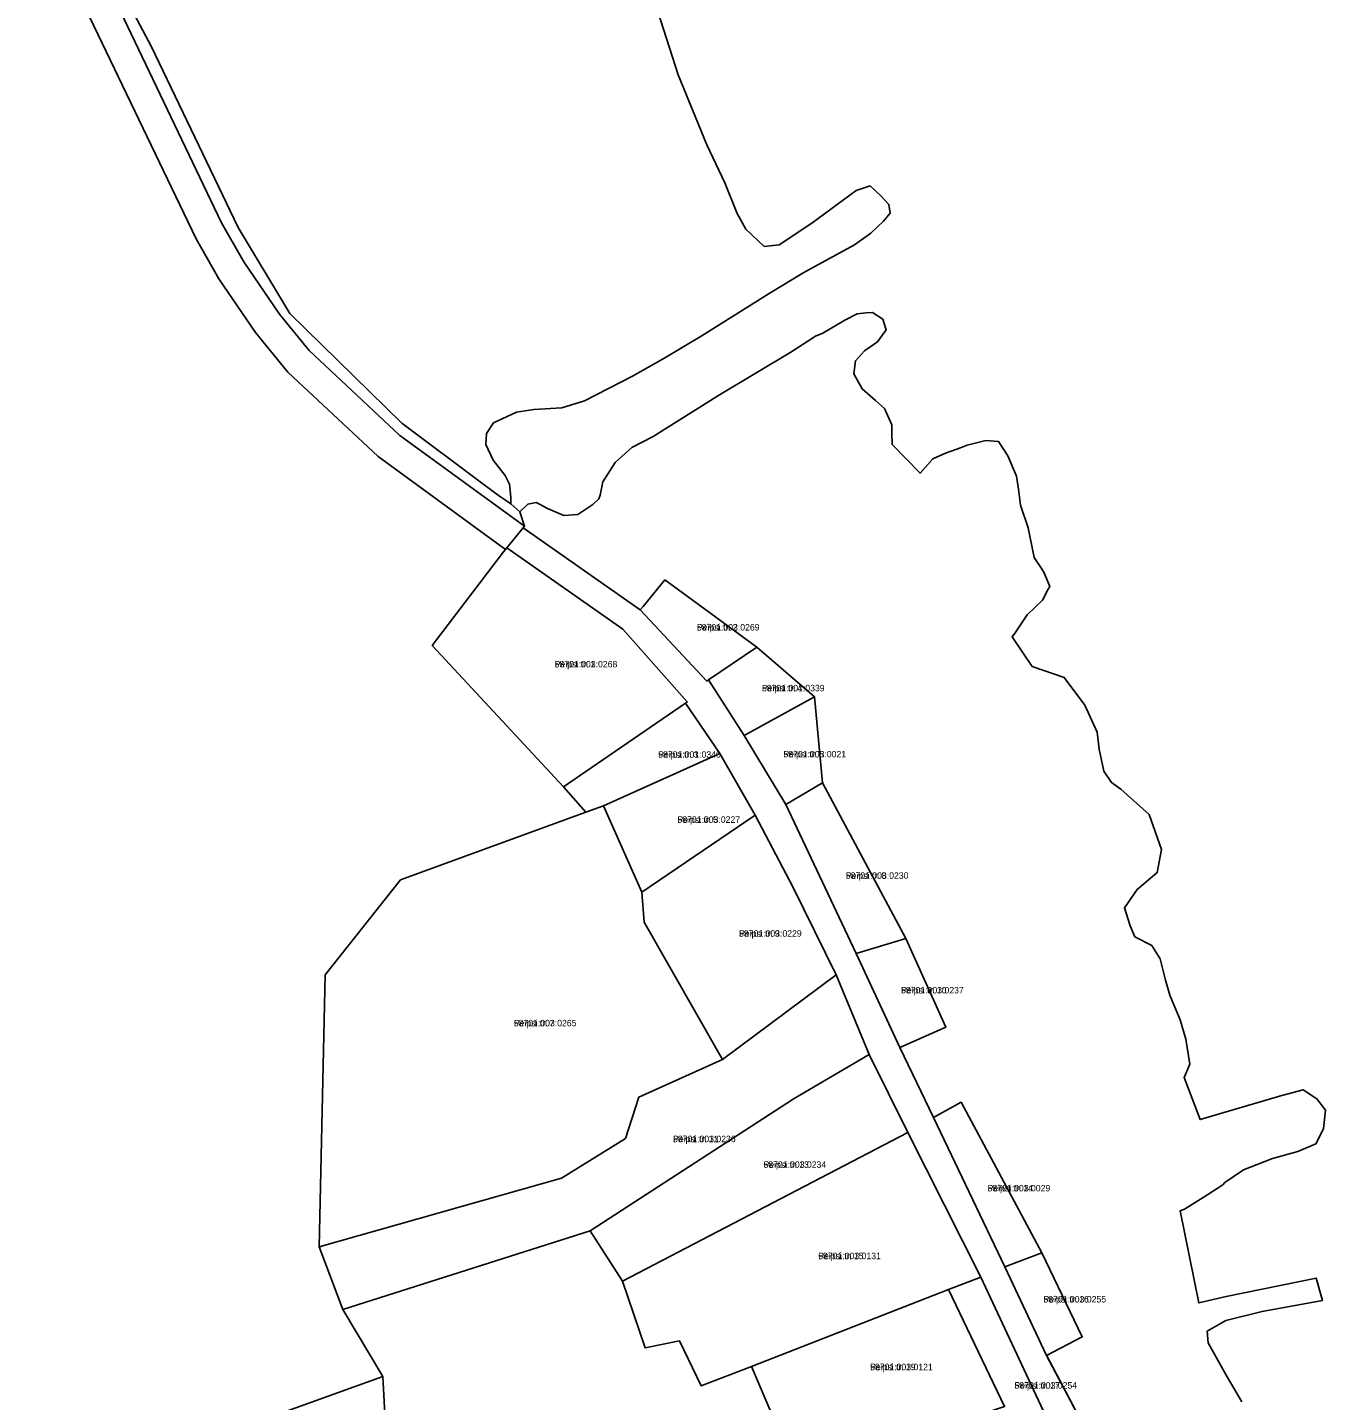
# Model space of a CAD drawing. Extents: x 663371 to 690098, y 6476568 to 6518353.
# Drawn here: x 687904.6 to 688205.1, y 6492520.5 to 6492838.4 of the extents above; entities that cross this region are included whole.
import ezdxf

# ---------------------------------------------------------------- set-up
doc = ezdxf.new("R2010")
doc.units = 0
for name, color, linetype in [('L_AADRESS', 7, 'Continuous'), ('PIIR', 7, 'Continuous'), ('TUNNUS', 7, 'Continuous')]:
    doc.layers.add(name, color=color, linetype=linetype)

msp = doc.modelspace()

# ---------------------------------------------------------------- linework, layer by layer
at = {"layer": 'PIIR'}
for points in [[(688049.77, 6492844.51), (688055.27, 6492827.42), (688061.86, 6492811.22), (688066.08, 6492802.43), (688068.94, 6492795.35), (688070.92, 6492791.66), (688075.15, 6492787.68), (688078.65, 6492788.09), (688086.21, 6492793.05), (688096.49, 6492800.61), (688099.67, 6492801.7), (688102.29, 6492799.35), (688104.01, 6492797.37), (688104.31, 6492795.41), (688102.77, 6492793.53), (688099.83, 6492790.75), (688096.07, 6492788.09), (688084.37, 6492781.68), (688076.35, 6492776.77), (688060.61, 6492766.88), (688051.8, 6492761.65), (688044.71, 6492757.64), (688033.59, 6492751.95), (688028.32, 6492750.34), (688021.86, 6492749.9), (688017.82, 6492749.35), (688012.52, 6492746.84), (688010.84, 6492744.37), (688010.74, 6492741.81), (688012.38, 6492738.22), (688015.2, 6492734.69), (688016.23, 6492732.65), (688016.48, 6492729.65), (688016.47, 6492728.13), (688015.77, 6492728.61), (688013.9, 6492729.9), (688010.04, 6492732.74), (687991.27, 6492746.81), (687965.32, 6492772.19), (687953.37, 6492792.06), (687933.3, 6492833.94), (687919.52, 6492859.99)], [(687919.52, 6492859.99), (687933.3, 6492833.94), (687953.37, 6492792.06), (687965.32, 6492772.19), (687991.27, 6492746.81), (688010.04, 6492732.74), (688013.9, 6492729.9), (688015.77, 6492728.61), (688016.47, 6492728.13), (688018.58, 6492726.23), (688019.67, 6492722.92), (687990.82, 6492743.9), (687969.78, 6492763.62), (687962.96, 6492772), (687954.7, 6492784.09), (687949.55, 6492793.19), (687925.27, 6492843.86)], [(687925.27, 6492843.86), (687949.55, 6492793.19), (687954.7, 6492784.09), (687962.96, 6492772), (687969.78, 6492763.62), (687990.82, 6492743.9), (688019.67, 6492722.92), (688019.36, 6492722.55), (688015.56, 6492717.9), (688015.25, 6492717.52), (687985.77, 6492739.07), (687964.9, 6492758.61), (687957.42, 6492767.74), (687948.89, 6492780.18), (687943.62, 6492789.47), (687919.02, 6492840.71)], [(687919.02, 6492840.71), (687943.62, 6492789.47), (687948.89, 6492780.18), (687957.42, 6492767.74), (687964.9, 6492758.61), (687985.77, 6492739.07), (688015.25, 6492717.52), (688014.84, 6492716.95), (687998.32, 6492695.33), (688028.7, 6492662.54), (688033.9, 6492656.68), (687990.98, 6492641.02), (687973.52, 6492619.07), (687972.11, 6492556.04), (687977.61, 6492541.58), (687986.85, 6492526.07), (687952.4, 6492513.63), (687860.02, 6492508.91)], [(688152.43, 6492508.44), (688140.62, 6492530.8), (688140.56, 6492530.91), (688148.8, 6492535.2), (688139.46, 6492554.68), (688120.75, 6492589.54), (688114.34, 6492586.01), (688106.61, 6492602.21), (688117.25, 6492606.93), (688107.96, 6492627.46), (688088.69, 6492663.47), (688086.82, 6492683.37), (688073.5, 6492694.93), (688052.19, 6492710.48), (688047.13, 6492704.29), (688046.49, 6492703.52), (688019.36, 6492722.55), (688019.67, 6492722.92), (688018.58, 6492726.23), (688020.46, 6492728.05), (688022.36, 6492728.38), (688023.15, 6492727.98), (688025.03, 6492727.04), (688028.76, 6492725.36), (688032, 6492725.63), (688035.52, 6492727.97), (688036.9, 6492729.22), (688037.19, 6492730.09), (688037.83, 6492733.17), (688040.63, 6492737.63), (688044.5, 6492741.11), (688049.47, 6492743.68), (688064.82, 6492753.35), (688081.32, 6492763.19), (688087.02, 6492766.91), (688088.78, 6492767.63), (688093.82, 6492770.64), (688096.67, 6492772.12), (688098.77, 6492772.3), (688100.25, 6492772.42), (688102.61, 6492770.84), (688103.25, 6492768.88), (688103.42, 6492768.36), (688101.37, 6492765.61), (688098.39, 6492763.53), (688096.29, 6492761.21), (688095.92, 6492758.16), (688097.82, 6492754.75), (688100.95, 6492752.03), (688103.01, 6492750.18), (688104.71, 6492746.35), (688104.75, 6492744.49), (688104.81, 6492741.85), (688111.25, 6492735.19), (688114.2, 6492738.5), (688117.18, 6492739.79), (688120.62, 6492741.03), (688122.14, 6492741.65), (688126.47, 6492742.72), (688129.45, 6492742.52), (688131.61, 6492739.17), (688133.61, 6492734.5), (688134.05, 6492731.49), (688134.48, 6492727.82), (688136.25, 6492722.57), (688137.67, 6492715.64), (688139.07, 6492713.55), (688139.94, 6492712.27), (688141.27, 6492708.97), (688140.95, 6492708.37), (688139.61, 6492705.76), (688136.09, 6492702.37), (688133.15, 6492697.97), (688132.58, 6492697.27), (688137.24, 6492690.46), (688144.65, 6492687.89), (688149.41, 6492681.45), (688152.3, 6492675.2), (688152.69, 6492671.32), (688153.8, 6492666.19), (688155.57, 6492663.57), (688157.72, 6492662.06), (688164.32, 6492656.15), (688167.19, 6492648.08), (688166.19, 6492642.71), (688161.5, 6492638.82), (688158.56, 6492634.52), (688159.94, 6492630.38), (688161, 6492627.84), (688164.89, 6492625.81), (688166.86, 6492622.75), (688168.09, 6492617.83), (688169.1, 6492614.31), (688169.88, 6492612.44), (688171.46, 6492608.64), (688172.77, 6492604.11), (688173.69, 6492598.38), (688172.4, 6492595.29), (688176.11, 6492585.54), (688195.01, 6492591.06), (688199.96, 6492592.42), (688203.11, 6492590.35), (688205.14, 6492587.74), (688204.7, 6492583.36), (688202.9, 6492579.92), (688198.76, 6492578.17), (688192.85, 6492576.52), (688186.14, 6492573.91), (688181.79, 6492570.97), (688181.35, 6492570.42), (688176.77, 6492567.48), (688172.51, 6492564.78), (688171.5, 6492564.42), (688175.82, 6492543.08), (688182.14, 6492544.52), (688202.96, 6492548.82), (688204.4, 6492543.61), (688190.49, 6492541.08), (688182.02, 6492539.01), (688177.77, 6492536.56), (688177.96, 6492533.83), (688180.94, 6492528.44), (688182.16, 6492526.32), (688183.13, 6492524.64), (688185.79, 6492520.2)], [(688139.77, 6492518.16), (688125.34, 6492549.07), (688108.45, 6492582.56), (688099.48, 6492600.59), (688091.87, 6492619.01), (688081.89, 6492639.28), (688073.08, 6492656.01), (688064.88, 6492670.29), (688056.94, 6492681.93), (688057.35, 6492682.21), (688042.45, 6492699.07), (688015.56, 6492717.9), (688019.36, 6492722.55), (688046.49, 6492703.52), (688061.87, 6492687.04), (688062.29, 6492687.32), (688070.57, 6492674.43), (688080.18, 6492658.44), (688096.49, 6492624.01), (688106.61, 6492602.21), (688114.34, 6492586.01), (688130.87, 6492551.39), (688140.56, 6492530.91), (688152.43, 6492508.44)]]:
    msp.add_lwpolyline(points, dxfattribs=at)
for points in [[(688056.94, 6492681.93), (688028.7, 6492662.54), (687998.32, 6492695.33), (688014.84, 6492716.95), (688015.25, 6492717.52), (688015.56, 6492717.9), (688042.45, 6492699.07), (688057.35, 6492682.21)], [(688047.13, 6492704.29), (688052.19, 6492710.48), (688073.5, 6492694.93), (688062.29, 6492687.32), (688061.87, 6492687.04), (688046.49, 6492703.52)], [(688062.29, 6492687.32), (688073.5, 6492694.93), (688086.82, 6492683.37), (688070.57, 6492674.43)], [(688028.7, 6492662.54), (688056.94, 6492681.93), (688064.88, 6492670.29), (688037.98, 6492658.17), (688033.9, 6492656.68)], [(688080.18, 6492658.44), (688070.57, 6492674.43), (688086.82, 6492683.37), (688088.69, 6492663.47)], [(688037.98, 6492658.17), (688064.88, 6492670.29), (688073.08, 6492656.01), (688046.83, 6492638.17)], [(688107.96, 6492627.46), (688096.49, 6492624.01), (688080.18, 6492658.44), (688088.69, 6492663.47)], [(688046.83, 6492638.17), (688047.38, 6492631.25), (688065.54, 6492599.41), (688046.12, 6492590.68), (688043.06, 6492581.18), (688028.21, 6492571.98), (687972.11, 6492556.04), (687973.52, 6492619.07), (687990.98, 6492641.02), (688033.9, 6492656.68), (688037.98, 6492658.17)], [(688046.83, 6492638.17), (688073.08, 6492656.01), (688081.89, 6492639.28), (688091.87, 6492619.01), (688065.54, 6492599.41), (688047.38, 6492631.25)], [(688117.25, 6492606.93), (688106.61, 6492602.21), (688096.49, 6492624.01), (688107.96, 6492627.46)], [(688065.54, 6492599.41), (688091.87, 6492619.01), (688099.48, 6492600.59), (688082.08, 6492590.41), (688034.88, 6492559.77), (687977.61, 6492541.58), (687972.11, 6492556.04), (688028.21, 6492571.98), (688043.06, 6492581.18), (688046.12, 6492590.68)], [(688082.08, 6492590.41), (688099.48, 6492600.59), (688108.45, 6492582.56), (688042.34, 6492548.11), (688034.88, 6492559.77)], [(688130.87, 6492551.39), (688114.34, 6492586.01), (688120.75, 6492589.54), (688139.46, 6492554.68)], [(688047.6, 6492532.68), (688042.34, 6492548.11), (688108.45, 6492582.56), (688125.34, 6492549.07), (688117.88, 6492546.17), (688072.21, 6492528.37), (688060.58, 6492523.84), (688055.58, 6492534.27)], [(687977.61, 6492541.58), (688034.88, 6492559.77), (688042.34, 6492548.11), (688047.6, 6492532.68), (688055.58, 6492534.27), (688060.58, 6492523.84), (688072.21, 6492528.37), (688080.45, 6492509), (688100.45, 6492508.81), (688091.5, 6492505.79), (688095.7, 6492497.39), (688072.78, 6492489.02), (688042.26, 6492489.34), (688040.92, 6492445.66), (688012.56, 6492458.29), (688017.36, 6492489.98), (688011.42, 6492506.84), (687987.57, 6492513.01), (687986.85, 6492526.07)], [(688140.56, 6492530.91), (688130.87, 6492551.39), (688139.46, 6492554.68), (688148.8, 6492535.2)], [(688139.77, 6492518.16), (688095.7, 6492497.39), (688091.5, 6492505.79), (688100.45, 6492508.81), (688130.83, 6492519.07), (688117.88, 6492546.17), (688125.34, 6492549.07)], [(688130.83, 6492519.07), (688100.45, 6492508.81), (688080.45, 6492509), (688072.21, 6492528.37), (688117.88, 6492546.17)], [(687955.96, 6492496.94), (687952.4, 6492513.63), (687986.85, 6492526.07), (687987.57, 6492513.01), (687988.32, 6492463.54), (687960.12, 6492464.96), (687956.75, 6492465.23), (687951.2, 6492466.48)]]:
    msp.add_lwpolyline(points, close=True, dxfattribs=at)

# ---------------------------------------------------------------- texts
at = {"layer": 'L_AADRESS'}
for s, p in [('Peipsi tn 2', (688059.59, 6492698.76)), ('Peipsi tn 1', (688026.66, 6492690.22)), ('Peipsi tn 4', (688074.65, 6492684.68)), ('Peipsi tn 3', (688050.62, 6492669.3)), ('Peipsi tn 6', (688079.63, 6492669.38)), ('Peipsi tn 5', (688055.09, 6492654.23)), ('Peipsi tn 8', (688094.07, 6492641.27)), ('Peipsi tn 9', (688069.35, 6492627.86)), ('Peipsi tn 10', (688106.87, 6492614.73)), ('Peipsi tn 7', (688017.2, 6492607.11)), ('Peipsi tn 11', (688054.06, 6492580.29)), ('Peipsi tn 13', (688075.02, 6492574.35)), ('Peipsi tn 14', (688126.9, 6492568.89)), ('Peipsi tn 15', (688087.68, 6492553.2)), ('Peipsi tn 16', (688139.83, 6492543.17)), ('Peipsi tn 19', (688099.7, 6492527.49)), ('Peipsi tn 17', (688133.12, 6492523.23))]:
    msp.add_text(s, height=1.5, dxfattribs=at).set_placement(p)
at = {"layer": 'TUNNUS'}
for s, p in [('58701:003:0269', (688059.59, 6492698.76)), ('58701:003:0268', (688026.66, 6492690.22)), ('58701:001:0339', (688074.65, 6492684.68)), ('58701:001:0340', (688050.62, 6492669.3)), ('58701:003:0021', (688079.63, 6492669.38)), ('58701:003:0227', (688055.09, 6492654.23)), ('58701:003:0230', (688094.07, 6492641.27)), ('58701:003:0229', (688069.35, 6492627.86)), ('58701:003:0237', (688106.87, 6492614.73)), ('58701:003:0265', (688017.2, 6492607.11)), ('58701:003:0236', (688054.06, 6492580.29)), ('58701:003:0234', (688075.02, 6492574.35)), ('58701:003:0029', (688126.9, 6492568.89)), ('58701:003:0131', (688087.68, 6492553.2)), ('58701:003:0255', (688139.83, 6492543.17)), ('58701:003:0121', (688099.7, 6492527.49)), ('58701:003:0254', (688133.12, 6492523.23))]:
    msp.add_text(s, height=1.5, dxfattribs=at).set_placement(p)

doc.saveas('drawing.dxf')
